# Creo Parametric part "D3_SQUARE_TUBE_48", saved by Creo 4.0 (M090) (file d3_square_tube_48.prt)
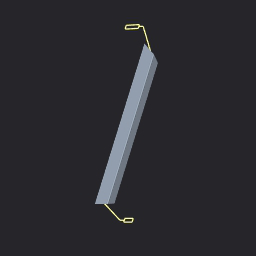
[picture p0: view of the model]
Units: Custom; MM, KILOGRAM, SECS
Materials in the file: STEEL

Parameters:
  BUW_NAME = "SQUARE TUBE"
  BUW_TYPE = "DIN EN 10210"
  BUW_SIZE = "60x60x3.0"
  BUW_LENGTH_STR = "855.2"
  PTC_MATERIAL_NAME = "STEEL"
  BUW_PROFIL_TYPE = "square_tube"
  BUW_PROFILE_PATH = "parts/profiles/steel_beams_mm/"
  BUW_PROFILE_NAME_LANG = "SQUARE TUBE"
  BUW_TAB_SEL_INFO = "2  0 2  3 19"
  MITRE_SYM_X_S = "|"
  MITRE_SYM_X_E = "\"
  MITRE_SYM_X = "|---\"
  MITRE_BOM_X = "X |---\"
  MITRE_SYM_Y_S = "/"
  MITRE_SYM_Y_E = "|"
  MITRE_SYM_Y = "/---|"
  MITRE_BOM_Y = "Y /---|"
  BUW_DOUBLE_TO_STR_INFO = "X_ROT_S2 2 X_ROT_E2 2 Y_ROT_S2 2 Y_ROT_E2 2"
  X_ROT_S2_STR = "90"
  X_ROT_E2_STR = "50"
  Y_ROT_S2_STR = "45"
  Y_ROT_E2_STR = "90"
  BOM_ANGLE_S = "Y 45°"
  BOM_ANGLE_E = "X 50°"
  EFX_ITEM_NR = "1"
  PROFIL_RASTER_POS = "X_0"
  BUW_OBJECT_ROLE = "PROFIL_SYSTEM_BORE_END_POINTS"
  PRO_UNIT_SYS = "Custom"

Other parameters: BUW_LENGTH, X_ROT_S2, X_ROT_E2, Y_ROT_S2, Y_ROT_E2, D8, D93, D94, d26, d8, d93, d94, d98, D98, D0, D4, D1, D5, SHEAR_MODULUS, THERM_EXPANSION_REF_TEMPERATURE, STRUCTURAL_DAMPING_COEFFICIENT, STRESS_LIMIT_FOR_TENSION, STRESS_LIMIT_FOR_COMPRESSION, STRESS_LIMIT_FOR_SHEAR, EMISSIVITY

Created from: SQUARE_TUBE.PRT

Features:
  1. datum plane "YZ"
  2. datum plane "XZ"
  3. datum plane "XY"
  4. coordinate system
  5. coordinate system
  6. coordinate system
  7. coordinate system
  8. datum plane "DTM3"
  9. datum plane "DTM4"
  10. datum plane "DTM5"
  11. protrusion
  12. round
  13. round
  14. datum axis
  15. datum point "PNT0"
  16. datum point
  17. annotation "Annotation 1"

Other named items: PROFIL_CUT_QUILT, PROFILE_LENGTH_DIM, CONTACT_SURF_3, CONTACT_SURF_2, CONTACT_SURF_1, CONTACT_SURF_0, E, START_SURFACE, END_SURFACE, SIDE_SURF_3, SIDE_SURF_0, SIDE_SURF_1, SIDE_SURF_2, EDGE_7_S, EDGE_7_E, EDGE_1_S, EDGE_1_E, EDGE_3_S, EDGE_3_E, EDGE_5_S, EDGE_5_E, EDGE_6_S, EDGE_4_S, EDGE_2_S, EDGE_0_S, EDGE_6_E, EDGE_4_E, EDGE_2_E, EDGE_0_E, CS0, CS_S, CS_E, CS3, AE_NOTE0, AE_NOTE1

Named dimensions: X_ROT_S, Y_ROT_S, Z_OFF_S, X_ROT_E, Y_ROT_E, Z_OFF_E, PC_L, BUW_LENGTH_Z_MIN, BUW_LENGTH_DIM

Layers: 00_PROFIL_DATUM, 00_PROFIL_DRW_HIDE, 00_PROFIL_END_CSYS, 00_PROFIL_GEOMETRY, 00_PROFIL_QUILT, 00_PROFIL_SIZE_NOTE

Notes: 60x60x3.0 | START

Surfaces: 10 plane, 8 cylinder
